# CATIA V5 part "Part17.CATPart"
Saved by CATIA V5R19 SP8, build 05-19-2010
Part number: Couronne_b
Bounding box of the stored display mesh (mm): x -1517.308 to -724.08, y 0 to 60, z -369.243 to 427.344
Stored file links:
  G:\EU_thinkMotion\CFAO_2010\MMS_groupe1\MMS_groupe1\OK\ppiault\piault\piault_cfao\Part17.CATPart
  D:\Catia\Finaltest.CATProduct
  G:\Catia Projet\CFAO2\Product2.CATProduct
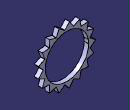
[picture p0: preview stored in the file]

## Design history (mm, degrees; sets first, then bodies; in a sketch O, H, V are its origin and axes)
External parameters (linked from other documents)
  External.DiametreRabatteur = 400 mm
Body1 (main body)
  Sketch1 on zx-plane, origin (0, 0, 0), H (-1, 0, 0), V (0, 0, 1)
    circle A1 centre (1117.3078, 29.0696) radius 300
    point P4 (1117.3078, 29.0696)
    arc A2 centre (1117.3078, 29.0696) radius 328 from (1439.9132, 88.3125) to (1439.8515, -30.5086) ccw
    point P5 (1517.3077, 28.8617)
    line L1 (1439.9132, 88.3125) -> (1517.3077, 28.8617)
    line L2 (1517.3077, 28.8617) -> (1439.8515, -30.5086)
    radius A1 = 300 {= External.DiametreRabatteur -100mm}
    radius A2 = 328 {= 0.82*External.DiametreRabatteur}
    distance P5 P4 = 400 {= External.DiametreRabatteur}
    angle L1 L2 = 75
  Pad1: profile Sketch1, direction (0, 1, 0), length 60
  CircPattern1: of Pad1, instances 18, angular step 21.1765, axis from start face of Pad1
